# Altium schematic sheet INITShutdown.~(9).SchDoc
size A4
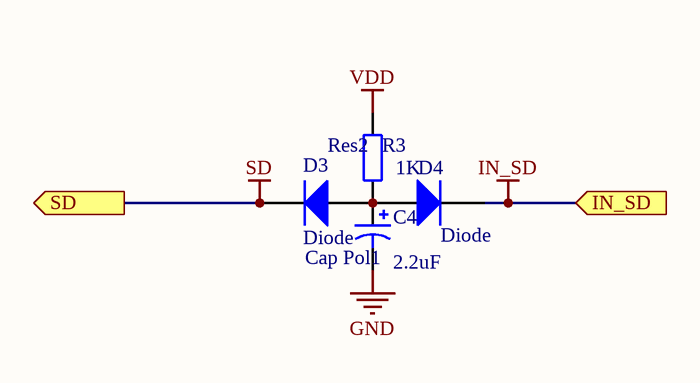
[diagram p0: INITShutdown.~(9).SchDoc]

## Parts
C4  Cap Pol1  value 2.2uF  [CAPPR2.5-6.3X5]
D3  Diode  [DO-204AL]
D4  Diode  [DO-204AL]
R3  Res2  value 1K  [AXIAL-0.3]

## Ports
IN_SD (in), SD (out)

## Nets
GND: C4.2
IN_SD: D4.2(K) ; port IN_SD
SD: D3.2(K) ; port SD
VDD: R3.2
NetC4_1: C4.1 D3.1(A) D4.1(A) R3.1

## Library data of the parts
C4 = Cap Pol1: Polarized Capacitor (Radial)
D3 D4 = Diode: Default Diode
R3 = Res2: Resistor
